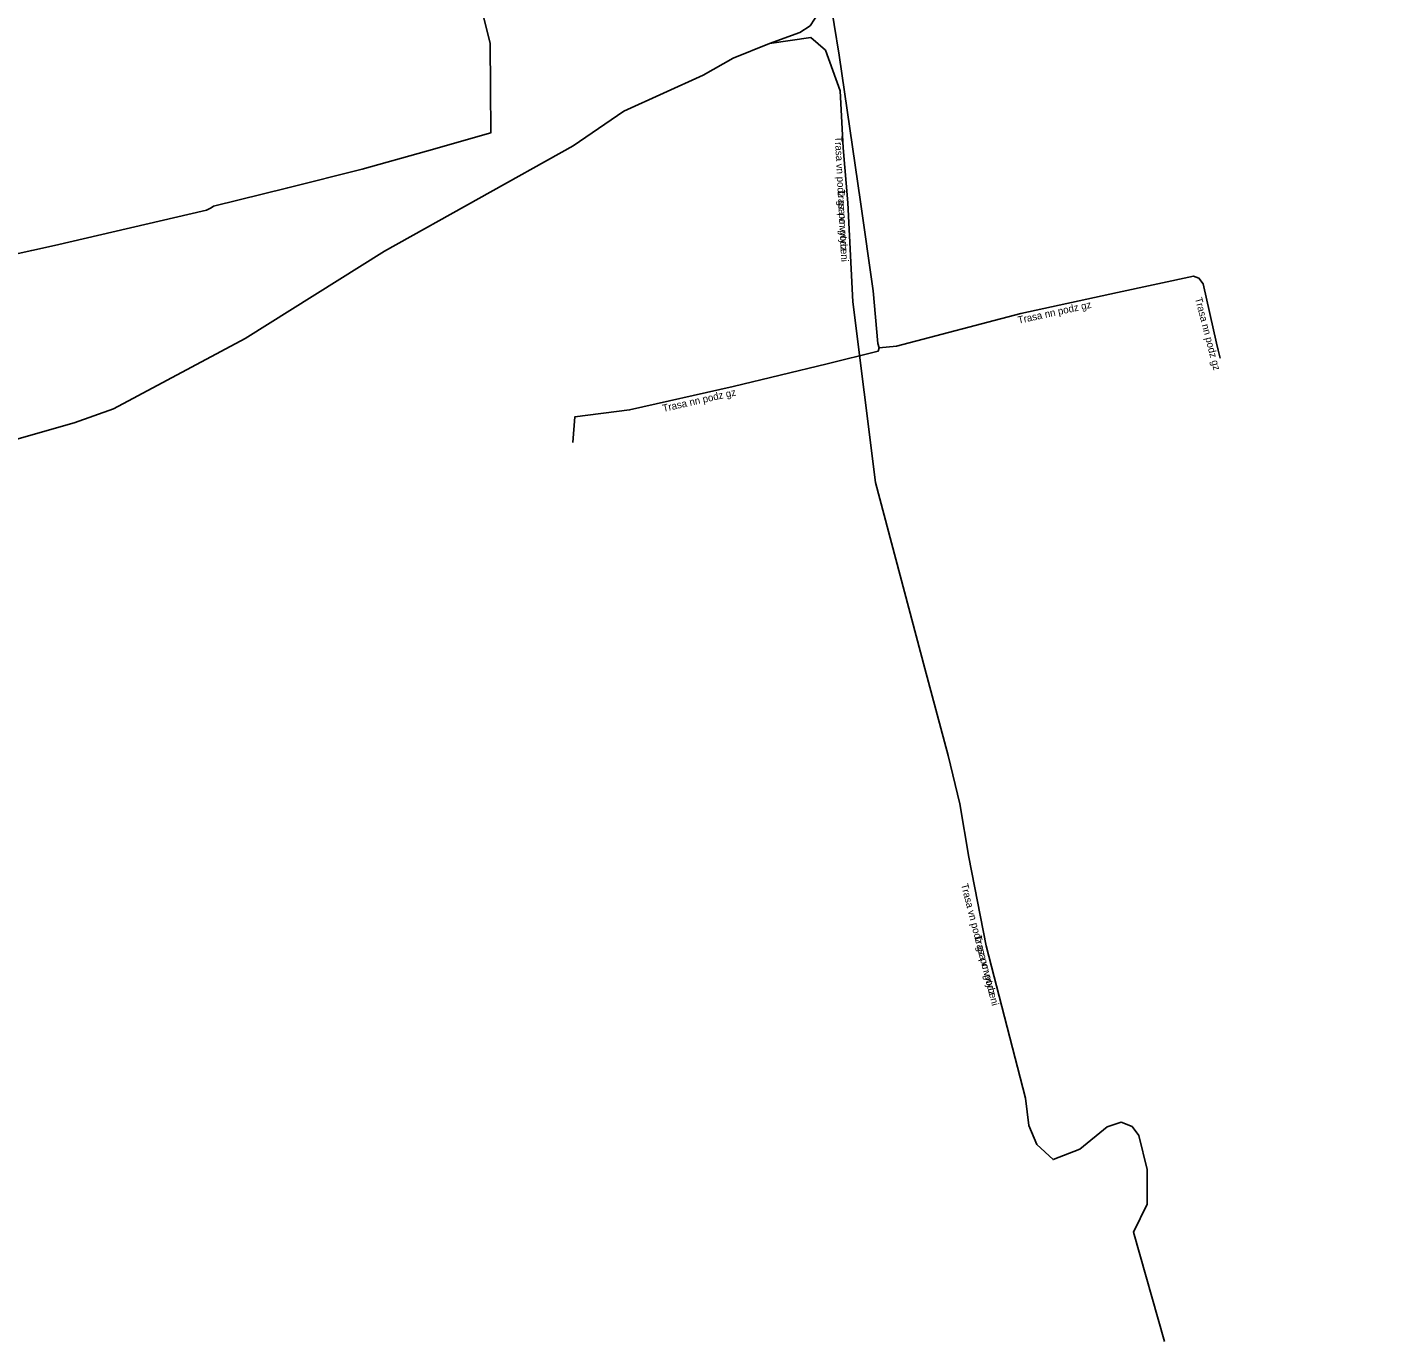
# Model space of a CAD drawing. Extents: x -473162 to -472638, y -1107075 to -1106812.
# Drawn here: x -472775.4 to -472680.8, y -1107074.5 to -1106984.1 of the extents above; entities that cross this region are included whole.
import ezdxf

# ---------------------------------------------------------------- set-up
doc = ezdxf.new("R2010")
doc.units = 0
for name, color, linetype in [('Popiskový text - Ostatní atributy Trasy', 7, 'Continuous'), ('Spojnice NN', 7, 'Continuous'), ('Spojnice VN', 7, 'Continuous')]:
    doc.layers.add(name, color=color, linetype=linetype)

msp = doc.modelspace()

# ---------------------------------------------------------------- linework, layer by layer
at = {"layer": 'Spojnice NN'}
for points in [[(-472716.74, -1107006.11), (-472716.829, -1107005.828), (-472717.159, -1107002.193), (-472718.018, -1106996.058), (-472719.498, -1106985.951), (-472721.212, -1106975.381), (-472720.698, -1106971.99), (-472719.099, -1106961.018), (-472718.599, -1106954.624), (-472718.111, -1106948.609), (-472717.883, -1106946.177), (-472711.958, -1106944.887), (-472706.08, -1106943.461), (-472705.663, -1106943.552)], [(-472744.895, -1106979.72), (-472743.535, -1106985.14), (-472743.512, -1106988.23), (-472743.49, -1106991.32), (-472747.925, -1106992.568), (-472752.36, -1106993.815), (-472757.475, -1106995.092), (-472762.59, -1106996.37), (-472762.762, -1106996.468), (-472763.075, -1106996.625), (-472768.31, -1106997.848), (-472773.545, -1106999.07), (-472775.108, -1106999.412), (-472776.67, -1106999.755)], [(-472716.74, -1107006.11), (-472715.55, -1107005.99), (-472706.98, -1107003.76), (-472700.31, -1107002.3), (-472695.09, -1107001.18), (-472694.71, -1107001.31), (-472694.41, -1107001.71), (-472693.499, -1107005.785)], [(-472693.499, -1107005.785), (-472693.39, -1107006.27), (-472693.243, -1107006.836)], [(-472737.838, -1107012.626), (-472737.709, -1107010.867), (-472733.924, -1107010.393), (-472726.786, -1107008.775), (-472720.307, -1107007.206), (-472716.81, -1107006.354), (-472716.74, -1107006.11)]]:
    msp.add_lwpolyline(points, dxfattribs=at)
at = {"layer": 'Spojnice VN'}
for points in [[(-472724.295, -1106985.16), (-472722.19, -1106984.41), (-472721.49, -1106983.94), (-472720.89, -1106983.03), (-472721.25, -1106981.06), (-472724.26, -1106973.25), (-472724.48, -1106970.21), (-472726.72, -1106956.69), (-472727.2, -1106953.53), (-472727.57, -1106948.89), (-472724.8, -1106947.66), (-472721.7, -1106947.22), (-472715.48, -1106945.68), (-472706.43, -1106943.46), (-472702.47, -1106942.65), (-472697.23, -1106941.34), (-472688.2, -1106939.17), (-472680.82, -1106937.5)], [(-472724.295, -1106985.16), (-472721.445, -1106984.75), (-472720.425, -1106985.62), (-472719.415, -1106988.41), (-472719.215, -1106992.335), (-472718.905, -1106996.12), (-472718.55, -1107002.955), (-472716.995, -1107015.385)], [(-472724.295, -1106985.16), (-472721.445, -1106984.75), (-472720.425, -1106985.62), (-472719.415, -1106988.41), (-472719.215, -1106992.335), (-472718.905, -1106996.12), (-472718.55, -1107002.955), (-472716.995, -1107015.385)], [(-472875.93, -1107028.105), (-472871, -1107031.825), (-472861.334, -1107033.124), (-472850.8, -1107030.635), (-472845.315, -1107029.36), (-472833.57, -1107026.445), (-472822.845, -1107023.715), (-472815.105, -1107022.245), (-472801.34, -1107019), (-472791.505, -1107016.55), (-472781.55, -1107013.95), (-472772.185, -1107011.27), (-472769.485, -1107010.31), (-472760.405, -1107005.475), (-472750.82, -1106999.465), (-472737.825, -1106992.205), (-472734.315, -1106989.81), (-472728.85, -1106987.34), (-472726.784, -1106986.168), (-472724.295, -1106985.16)], [(-472875.93, -1107028.105), (-472871, -1107031.825), (-472861.334, -1107033.124), (-472850.8, -1107030.635), (-472845.315, -1107029.36), (-472833.57, -1107026.445), (-472822.845, -1107023.715), (-472815.105, -1107022.245), (-472801.34, -1107019), (-472791.505, -1107016.55), (-472781.55, -1107013.95), (-472772.185, -1107011.27), (-472769.485, -1107010.31), (-472760.405, -1107005.475), (-472750.82, -1106999.465), (-472737.825, -1106992.205), (-472734.315, -1106989.81), (-472728.85, -1106987.34), (-472726.784, -1106986.168), (-472724.295, -1106985.16)], [(-472716.995, -1107015.385), (-472713.58, -1107028.195), (-472711.99, -1107034.185), (-472711.18, -1107037.515), (-472710.57, -1107041.2), (-472709.355, -1107047.29), (-472706.66, -1107057.79), (-472706.42, -1107059.68), (-472705.88, -1107060.975), (-472704.76, -1107062.02), (-472702.915, -1107061.3), (-472701.04, -1107059.755), (-472700.075, -1107059.45), (-472699.31, -1107059.75), (-472698.84, -1107060.35), (-472698.28, -1107062.705), (-472698.285, -1107065.095), (-472699.21, -1107067.025), (-472697.089, -1107074.548)], [(-472716.995, -1107015.385), (-472713.58, -1107028.195), (-472711.99, -1107034.185), (-472711.18, -1107037.515), (-472710.57, -1107041.2), (-472709.355, -1107047.29), (-472706.66, -1107057.79), (-472706.42, -1107059.68), (-472705.88, -1107060.975), (-472704.76, -1107062.02), (-472702.915, -1107061.3), (-472701.04, -1107059.755), (-472700.075, -1107059.45), (-472699.31, -1107059.75), (-472698.84, -1107060.35), (-472698.28, -1107062.705), (-472698.285, -1107065.095), (-472699.21, -1107067.025), (-472697.089, -1107074.548)]]:
    msp.add_lwpolyline(points, dxfattribs=at)

# ---------------------------------------------------------------- texts
at = {"layer": 'Popiskový text - Ostatní atributy Trasy'}
for s, rotation, p in [('Trasa vn podz gz po vytyceni', 272.97319, (-472719.793, -1106991.555)), ('Trasa vn podz', 272.97319, (-472719.602, -1106995.236)), ('Trasa nn podz gz', 284.55904, (-472694.987, -1107002.707)), ('Trasa nn podz gz', 12.34677, (-472707.131, -1107004.459)), ('Trasa nn podz gz', 12.76653, (-472731.599, -1107010.532)), ('Trasa vn podz gz po vytyceni', 284.39518, (-472711.108, -1107043.074)), ('Trasa vn podz', 284.39518, (-472710.192, -1107046.643))]:
    msp.add_text(s, height=0.5, rotation=rotation, dxfattribs=at).set_placement(p)

doc.saveas('drawing.dxf')
